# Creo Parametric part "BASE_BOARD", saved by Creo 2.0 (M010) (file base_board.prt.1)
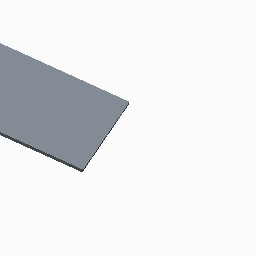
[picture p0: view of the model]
Units: Inch lbm Second (Pro/E Default); INCH, POUND, SECS

Created from: INLBS_PART_SOLID.PRT

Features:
  1. datum plane "RIGHT"
  2. datum plane "TOP"
  3. datum plane "FRONT"
  4. coordinate system
  5. sketch "Sketch 1"
  6. extrusion "Extrude 1", "Sketch 1"

Surfaces: 9 plane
